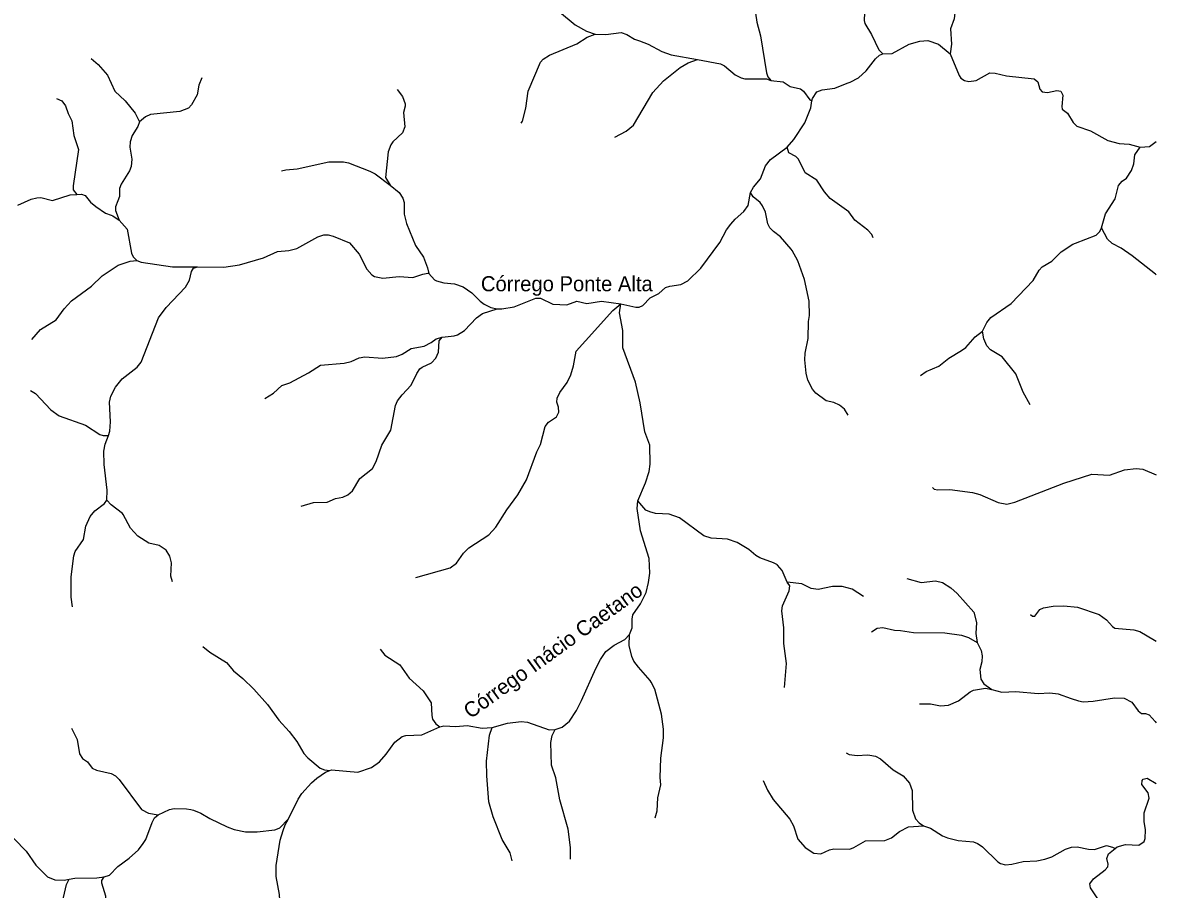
# Model space of a CAD drawing. Extents: x 473.9 to 500, y 7733.1 to 7760.8.
# Drawn here: x 492.5 to 500, y 7739.47 to 7745.21 of the extents above; entities that cross this region are included whole.
import ezdxf
from ezdxf.enums import TextEntityAlignment as Align

# ---------------------------------------------------------------- set-up
doc = ezdxf.new("R2010")
doc.units = 0
doc.header["$LTSCALE"] = 0.032
doc.layers.add('61', color=7, linetype='Continuous')
doc.layers.add('7', color=7, linetype='Continuous', lineweight=25)

msp = doc.modelspace()

# ---------------------------------------------------------------- linework, layer by layer
at = {"layer": '7'}
for points in [[(498.741, 7745.8896), (498.7715, 7745.8231), (498.7848, 7745.7768), (498.7909, 7745.7442), (498.7909, 7745.6881), (498.7725, 7745.5809), (498.741, 7745.4838), (498.6718, 7745.3155), (498.6628, 7745.2366), (498.6378, 7745.1688), (498.6434, 7745.0688), (498.6358, 7745.0043)], [(497.7661, 7745.6796), (497.8066, 7745.6735), (497.9181, 7745.6109), (497.9471, 7745.5857), (498.0085, 7745.5035), (498.0327, 7745.4566), (498.0646, 7745.3671), (498.0709, 7745.3229), (498.0654, 7745.224), (498.0697, 7745.2044), (498.115, 7745.1324), (498.1628, 7745.0297), (498.1897, 7745.0029)], [(495.744, 7745.4219), (495.9039, 7745.3332), (496.0106, 7745.3071), (496.0494, 7745.2818), (496.1528, 7745.1957), (496.2285, 7745.1548), (496.2851, 7745.1339)], [(497.3215, 7745.4526), (497.3558, 7745.2131), (497.3799, 7745.1233), (497.4205, 7744.8774), (497.4292, 7744.8521), (497.4487, 7744.828)], [(495.7972, 7744.5455), (495.8059, 7744.5583), (495.8275, 7744.6442), (495.8417, 7744.7558), (495.9231, 7744.9491), (495.9409, 7744.9675), (495.9837, 7744.9952), (496.1637, 7745.0705), (496.2327, 7745.1134), (496.2851, 7745.1339)], [(496.2851, 7745.1339), (496.3563, 7745.1326), (496.4584, 7745.1444), (496.4956, 7745.1311), (496.5463, 7745.1017), (496.5784, 7745.0899), (496.637, 7745.0685), (496.7274, 7745.0185), (496.7894, 7744.9968), (496.9629, 7744.9654)], [(498.1897, 7745.0029), (498.2513, 7745.006), (498.3641, 7745.0674), (498.4342, 7745.0874), (498.4882, 7745.0923), (498.5581, 7745.0685), (498.6358, 7745.0043)], [(492.9505, 7744.9735), (492.9975, 7744.9341), (493.0576, 7744.862), (493.1069, 7744.7558), (493.176, 7744.6923), (493.2412, 7744.6119), (493.2692, 7744.5544)], [(496.4169, 7744.4519), (496.4912, 7744.4917), (496.5402, 7744.5311), (496.6686, 7744.7468), (496.7373, 7744.826), (496.8477, 7744.9137), (496.9009, 7744.9451), (496.9629, 7744.9654)], [(496.9629, 7744.9654), (497.1146, 7744.9387), (497.1414, 7744.9241), (497.2116, 7744.8643), (497.2527, 7744.8443), (497.2768, 7744.8383), (497.4208, 7744.8375), (497.4487, 7744.828)], [(497.7209, 7744.6936), (497.7242, 7744.7076), (497.7535, 7744.7531), (497.7888, 7744.766), (497.8721, 7744.7764), (497.9545, 7744.8086), (497.9744, 7744.8164), (498.0293, 7744.8458), (498.0803, 7744.8917), (498.1412, 7744.9711), (498.1679, 7744.994), (498.1897, 7745.0029)], [(498.6358, 7745.0043), (498.6957, 7744.8602), (498.706, 7744.8431), (498.7303, 7744.8284), (498.7598, 7744.8213), (498.8066, 7744.8269), (498.8971, 7744.8784), (498.9324, 7744.8759), (499.0083, 7744.8575), (499.1919, 7744.8384), (499.2159, 7744.8186), (499.2296, 7744.7709), (499.2438, 7744.7524), (499.2791, 7744.7477), (499.3418, 7744.7604), (499.3684, 7744.7561), (499.3818, 7744.7309), (499.3739, 7744.6545), (499.3778, 7744.6372), (499.4123, 7744.6105), (499.4486, 7744.5492), (499.4739, 7744.526), (499.5641, 7744.4949), (499.678, 7744.4308), (499.7543, 7744.4093), (499.8192, 7744.4052), (499.8941, 7744.3865)], [(493.6818, 7744.8453), (493.6637, 7744.7972), (493.6511, 7744.7314), (493.6146, 7744.6667), (493.5941, 7744.6452), (493.5379, 7744.6226), (493.3437, 7744.6029), (493.3105, 7744.5863), (493.2692, 7744.5544)], [(497.4487, 7744.828), (497.5297, 7744.8191), (497.5767, 7744.7879), (497.6457, 7744.7717), (497.6644, 7744.7564), (497.7066, 7744.6991), (497.7209, 7744.6936)], [(494.9755, 7744.7672), (495.0107, 7744.722), (495.028, 7744.6737), (495.0289, 7744.6574), (495.017, 7744.6156), (495.0266, 7744.5198), (495.0113, 7744.4806), (494.9476, 7744.4216), (494.9336, 7744.402), (494.9152, 7744.3542), (494.8975, 7744.1843), (494.9301, 7744.134)], [(492.7213, 7744.7074), (492.7551, 7744.693), (492.7809, 7744.6599), (492.7971, 7744.6083), (492.8218, 7744.5602), (492.8355, 7744.464), (492.8663, 7744.3711), (492.8305, 7744.1289), (492.8313, 7744.1025), (492.8543, 7744.0724)], [(497.5573, 7744.3865), (497.6012, 7744.4357), (497.6731, 7744.546), (497.7132, 7744.6471), (497.7209, 7744.6936)], [(493.2692, 7744.5544), (493.26, 7744.523), (493.2214, 7744.464), (493.2074, 7744.4201), (493.2066, 7744.3857), (493.2185, 7744.3074), (493.2155, 7744.2567), (493.2041, 7744.2289), (493.1484, 7744.1417), (493.1376, 7744.1123), (493.1374, 7744.0586), (493.1269, 7744.0304), (493.112, 7743.9902), (493.1112, 7743.9654), (493.1349, 7743.9021)], [(497.3129, 7744.0855), (497.3336, 7744.1219), (497.3792, 7744.1762), (497.4141, 7744.2622), (497.4466, 7744.3052), (497.5573, 7744.3865)], [(498.1253, 7743.7856), (498.1171, 7743.8073), (498.0904, 7743.8358), (498.0052, 7743.9017), (497.9648, 7743.9581), (497.8404, 7744.0457), (497.8031, 7744.0904), (497.7524, 7744.1665), (497.6758, 7744.2167), (497.6757, 7744.2167), (497.6313, 7744.3061), (497.6147, 7744.3242), (497.5677, 7744.349), (497.5573, 7744.3865)], [(499.6368, 7743.8523), (499.6626, 7743.9454), (499.7273, 7744.0441), (499.7446, 7744.1135), (499.7493, 7744.1324), (499.7748, 7744.1615), (499.8016, 7744.1797), (499.8357, 7744.2324), (499.8504, 7744.2748), (499.858, 7744.3344), (499.8941, 7744.3865)], [(499.8941, 7744.3865), (499.9556, 7744.3908), (499.9993, 7744.423), (500, 7744.4235)], [(494.2108, 7744.2287), (494.2388, 7744.2361), (494.3143, 7744.2415), (494.5231, 7744.2889), (494.6213, 7744.2883), (494.6534, 7744.2818), (494.7951, 7744.2271), (494.8288, 7744.2094), (494.9301, 7744.134)], [(494.9301, 7744.134), (494.9886, 7744.0856), (495.0137, 7744.0476), (495.0217, 7744.0191), (495.0227, 7743.942), (495.037, 7743.8793), (495.0971, 7743.7349), (495.1494, 7743.6577), (495.1771, 7743.5866), (495.1851, 7743.5489)], [(492.4652, 7744.002), (492.5527, 7744.0411), (492.5912, 7744.0508), (492.6179, 7744.0515), (492.6949, 7744.0333), (492.8109, 7744.0692), (492.8543, 7744.0724)], [(492.8543, 7744.0724), (492.8862, 7744.0748), (492.9099, 7744.0649), (492.9462, 7744.0218), (492.9806, 7743.992), (493.046, 7743.948), (493.0818, 7743.9353), (493.0945, 7743.9308), (493.1349, 7743.9021)], [(496.4561, 7743.3474), (496.5542, 7743.3262), (496.578, 7743.3269), (496.6004, 7743.3381), (496.6508, 7743.3874), (496.7079, 7743.4174), (496.7513, 7743.4559), (496.78, 7743.4655), (496.8525, 7743.4756), (496.9, 7743.4999), (496.9843, 7743.584), (497.1106, 7743.7545), (497.1555, 7743.8379), (497.1828, 7743.8765), (497.2117, 7743.91), (497.2697, 7743.9608), (497.298, 7743.9996), (497.3129, 7744.0855)], [(497.96, 7742.6112), (497.9359, 7742.6504), (497.9025, 7742.6782), (497.8651, 7742.6939), (497.8153, 7742.7049), (497.7458, 7742.7573), (497.7246, 7742.7827), (497.6941, 7742.8433), (497.6814, 7742.8893), (497.6741, 7742.9775), (497.6765, 7743.0216), (497.6957, 7743.1186), (497.6973, 7743.2315), (497.7037, 7743.27), (497.7021, 7743.3661), (497.6725, 7743.5101), (497.6283, 7743.6339), (497.5892, 7743.7022), (497.5842, 7743.7109), (497.5119, 7743.792), (497.4653, 7743.8264), (497.4425, 7743.8513), (497.4297, 7743.8787), (497.4122, 7743.9552), (497.3924, 7743.9976), (497.3774, 7744.0188), (497.3307, 7744.0575), (497.3129, 7744.0855)], [(493.1349, 7743.9021), (493.1886, 7743.8427), (493.2166, 7743.684), (493.2288, 7743.6599), (493.2532, 7743.6348)], [(498.8493, 7743.1666), (498.8785, 7743.2256), (498.9045, 7743.2585), (499.0393, 7743.3515), (499.1848, 7743.5027), (499.2249, 7743.5717), (499.2439, 7743.5938), (499.3086, 7743.6314), (499.3704, 7743.6921), (499.4482, 7743.7433), (499.4659, 7743.7503), (499.6023, 7743.804), (499.6266, 7743.8278), (499.6368, 7743.8523)], [(500, 7743.5397), (499.9935, 7743.5448), (499.8394, 7743.6654), (499.767, 7743.7164), (499.7082, 7743.7472), (499.6772, 7743.7767), (499.6368, 7743.8523)], [(493.6534, 7743.5935), (493.8276, 7743.5906), (493.9319, 7743.6077), (494.0917, 7743.6534), (494.1839, 7743.6948), (494.258, 7743.7013), (494.3122, 7743.7146), (494.4505, 7743.7919), (494.4894, 7743.8046), (494.5194, 7743.8047), (494.5511, 7743.7975), (494.6603, 7743.7516), (494.723, 7743.6779), (494.7746, 7743.5773), (494.8078, 7743.5407), (494.8253, 7743.5298), (494.8809, 7743.5185), (494.9889, 7743.529), (495.0786, 7743.5219), (495.1457, 7743.5446), (495.1792, 7743.5523), (495.1851, 7743.5489)], [(492.5575, 7743.1115), (492.614, 7743.1777), (492.718, 7743.2432), (492.7714, 7743.3153), (492.819, 7743.3675), (492.952, 7743.4659), (493.0237, 7743.5329), (493.1287, 7743.6042), (493.2089, 7743.6307), (493.2532, 7743.6348)], [(493.2532, 7743.6348), (493.2816, 7743.6235), (493.4877, 7743.5939), (493.6534, 7743.5935)], [(493.0645, 7742.4768), (493.0726, 7742.5062), (493.0775, 7742.5673), (493.0711, 7742.697), (493.0796, 7742.7358), (493.1121, 7742.7958), (493.1563, 7742.8517), (493.2536, 7742.9281), (493.2806, 7742.961), (493.3962, 7743.2565), (493.4475, 7743.3234), (493.5755, 7743.4586), (493.6009, 7743.5053), (493.6141, 7743.5624), (493.6277, 7743.5848), (493.6534, 7743.5935)], [(495.1851, 7743.5489), (495.2222, 7743.5075), (495.2352, 7743.5013), (495.2852, 7743.4873), (495.3545, 7743.48), (495.4122, 7743.4607), (495.4694, 7743.4212), (495.5238, 7743.3659), (495.5521, 7743.3453), (495.5953, 7743.3249), (495.6373, 7743.3161)], [(495.6373, 7743.3161), (495.6675, 7743.3148), (495.749, 7743.329), (495.8936, 7743.3858), (495.9241, 7743.3868), (496.0056, 7743.3454), (496.0982, 7743.342), (496.1654, 7743.366), (496.2311, 7743.3495), (496.3282, 7743.3653), (496.4561, 7743.3474)], [(495.0995, 7741.5364), (495.3269, 7741.601), (495.3671, 7741.6317), (495.4142, 7741.6963), (495.449, 7741.7329), (495.5817, 7741.8189), (495.6295, 7741.8692), (495.7007, 7741.9852), (495.775, 7742.0831), (495.8314, 7742.1825), (495.9001, 7742.3682), (495.9235, 7742.4162), (495.9555, 7742.5365), (495.978, 7742.5649), (496.0302, 7742.6002), (496.0456, 7742.6317), (496.044, 7742.664), (496.0329, 7742.6974), (496.034, 7742.7232), (496.053, 7742.7619), (496.1012, 7742.8263), (496.1252, 7742.8786), (496.1434, 7742.938), (496.1596, 7743.0345), (496.2221, 7743.1035), (496.4037, 7743.304), (496.4561, 7743.3474)], [(495.2741, 7743.1282), (495.3518, 7743.1358), (495.3747, 7743.1437), (495.4216, 7743.1728), (495.501, 7743.2561), (495.5395, 7743.2839), (495.6373, 7743.3161)], [(496.5682, 7742.0447), (496.6188, 7742.1631), (496.6428, 7742.2382), (496.6501, 7742.287), (496.6485, 7742.4117), (496.6142, 7742.5015), (496.5835, 7742.6933), (496.5524, 7742.8299), (496.4687, 7743.0561), (496.4697, 7743.1728), (496.4466, 7743.2892), (496.4561, 7743.3474)], [(498.4383, 7742.874), (498.4763, 7742.9005), (498.5603, 7742.9349), (498.6276, 7742.9879), (498.711, 7743.0392), (498.7399, 7743.06), (498.8014, 7743.1305), (498.8493, 7743.1666)], [(499.1655, 7742.68), (499.1187, 7742.7635), (499.0691, 7742.885), (498.9799, 7742.9967), (498.9026, 7743.0445), (498.8791, 7743.0702), (498.8587, 7743.1176), (498.8493, 7743.1666)], [(494.1004, 7742.7211), (494.156, 7742.7576), (494.2127, 7742.8081), (494.2647, 7742.8252), (494.3889, 7742.8913), (494.467, 7742.9428), (494.6236, 7742.9557), (494.6707, 7742.9669), (494.7235, 7742.9901), (494.7604, 7742.9965), (494.8791, 7742.9885), (494.9703, 7743), (495.0084, 7743.0143), (495.0683, 7743.0526), (495.1537, 7743.0686), (495.2011, 7743.0929), (495.2327, 7743.1167), (495.2741, 7743.1282)], [(494.3401, 7742.0074), (494.4218, 7742.0336), (494.5129, 7742.0352), (494.5674, 7742.0593), (494.6158, 7742.0675), (494.649, 7742.0841), (494.6788, 7742.11), (494.7273, 7742.1913), (494.8123, 7742.257), (494.8364, 7742.3042), (494.8741, 7742.4133), (494.9341, 7742.5108), (494.9636, 7742.6744), (494.977, 7742.7057), (495.0076, 7742.7468), (495.0686, 7742.8108), (495.1045, 7742.8869), (495.1265, 7742.9169), (495.1399, 7742.9289), (495.2026, 7742.9584), (495.232, 7742.9888), (495.2485, 7743.0288), (495.2535, 7743.1028), (495.2741, 7743.1282)], [(492.5479, 7742.7734), (492.5821, 7742.755), (492.6832, 7742.6459), (492.7377, 7742.6075), (492.9125, 7742.5442), (493.0072, 7742.4834), (493.0294, 7742.4754), (493.0645, 7742.4768)], [(493.0534, 7742.0489), (493.0566, 7742.1142), (493.0358, 7742.2847), (493.0342, 7742.3722), (493.0434, 7742.4195), (493.0645, 7742.4768)], [(498.5176, 7742.131), (498.5297, 7742.1219), (498.5546, 7742.117), (498.6327, 7742.1177), (498.7826, 7742.0994), (498.8317, 7742.0855), (498.954, 7742.0334), (499.0113, 7742.0224), (499.0642, 7742.0346), (499.3884, 7742.16), (499.5731, 7742.2204), (499.6895, 7742.214), (499.7884, 7742.2492), (499.866, 7742.258), (499.9099, 7742.2525), (499.9993, 7742.2165), (500, 7742.2162)], [(492.8259, 7741.3427), (492.8169, 7741.406), (492.8176, 7741.5408), (492.8349, 7741.6803), (492.845, 7741.708), (492.8985, 7741.788), (492.9155, 7741.8762), (492.9425, 7741.9407), (492.9734, 7741.9776), (493.0387, 7742.0253), (493.0534, 7742.0489)], [(493.4885, 7741.5071), (493.4776, 7741.5452), (493.4815, 7741.6341), (493.4712, 7741.6763), (493.4462, 7741.7176), (493.4009, 7741.747), (493.3311, 7741.7624), (493.2589, 7741.8087), (493.2099, 7741.8617), (493.1613, 7741.9534), (493.1583, 7741.9591), (493.0825, 7742.0173), (493.0534, 7742.0489)], [(496.514, 7741.1576), (496.5298, 7741.2022), (496.53, 7741.261), (496.5361, 7741.2888), (496.5866, 7741.3615), (496.6237, 7741.437), (496.6398, 7741.502), (496.6469, 7741.5639), (496.6436, 7741.6623), (496.5853, 7741.8456), (496.5628, 7741.9924), (496.5682, 7742.0447)], [(497.5571, 7741.5053), (497.5227, 7741.5826), (497.4936, 7741.6182), (497.493, 7741.6189), (497.4669, 7741.6337), (497.3758, 7741.6663), (497.3482, 7741.6824), (497.3031, 7741.7215), (497.2252, 7741.7685), (497.1624, 7741.7897), (497.053, 7741.7962), (497.0051, 7741.8119), (496.8449, 7741.9321), (496.7756, 7741.9558), (496.7319, 7741.9582), (496.6851, 7741.9607), (496.6476, 7741.9708), (496.6208, 7741.9819), (496.5682, 7742.0447)], [(497.5389, 7740.8086), (497.5513, 7740.9672), (497.5338, 7741.1), (497.5337, 7741.202), (497.5218, 7741.3148), (497.5268, 7741.3479), (497.5706, 7741.4485), (497.5738, 7741.4816), (497.5571, 7741.5053)], [(498.0626, 7741.4094), (497.9862, 7741.4578), (497.9209, 7741.4762), (497.8557, 7741.4763), (497.7618, 7741.4572), (497.7159, 7741.4638), (497.6537, 7741.494), (497.5571, 7741.5053)], [(498.3476, 7741.5287), (498.4442, 7741.5029), (498.5383, 7741.5133), (498.5843, 7741.5027), (498.6396, 7741.4672), (498.6822, 7741.4304), (498.7912, 7741.3065), (498.8092, 7741.2389), (498.8062, 7741.1653), (498.8143, 7741.105)], [(499.1679, 7741.2918), (499.1809, 7741.2803), (499.1952, 7741.2794), (499.23, 7741.3252), (499.2534, 7741.3361), (499.3173, 7741.3457), (499.3879, 7741.3481), (499.4775, 7741.3392), (499.6213, 7741.2913), (499.6707, 7741.2556), (499.7095, 7741.2112), (499.7263, 7741.2014), (499.8503, 7741.1886), (499.8919, 7741.179), (499.9881, 7741.122), (500, 7741.1149)], [(498.1141, 7741.1753), (498.153, 7741.1998), (498.1888, 7741.2046), (498.2678, 7741.1862), (498.3066, 7741.1861), (498.3929, 7741.1717), (498.6007, 7741.1701), (498.7114, 7741.1539), (498.7573, 7741.138), (498.8143, 7741.105)], [(496.0215, 7740.5294), (496.0678, 7740.5441), (496.1166, 7740.5842), (496.1614, 7740.6551), (496.1946, 7740.7216), (496.2895, 7740.9338), (496.3206, 7740.9926), (496.357, 7741.0453), (496.4127, 7741.0869), (496.4821, 7741.125), (496.514, 7741.1576)], [(496.6829, 7739.9448), (496.6973, 7739.9899), (496.6999, 7740.0772), (496.7207, 7740.1639), (496.716, 7740.2108), (496.7215, 7740.3402), (496.7383, 7740.4742), (496.7383, 7740.5314), (496.724, 7740.6317), (496.681, 7740.7962), (496.6565, 7740.8422), (496.6503, 7740.8539), (496.5728, 7740.9413), (496.5422, 7740.9817), (496.5278, 7741.0131), (496.5115, 7741.0855), (496.514, 7741.1576)], [(493.6898, 7741.0785), (493.7359, 7741.0425), (493.8469, 7740.973), (493.8928, 7740.9175), (493.9544, 7740.8679), (494.0275, 7740.7957), (494.1179, 7740.6941), (494.192, 7740.5911), (494.2614, 7740.5159), (494.3107, 7740.449), (494.3582, 7740.3702), (494.3849, 7740.3413), (494.4653, 7740.2743), (494.4944, 7740.2626), (494.5297, 7740.2574)], [(494.8622, 7741.0612), (494.8928, 7741.0225), (494.9935, 7740.9577), (495.054, 7740.8692), (495.1483, 7740.7852), (495.2005, 7740.706), (495.2041, 7740.6212), (495.2102, 7740.598), (495.2315, 7740.5659), (495.2575, 7740.5464)], [(498.8143, 7741.105), (498.8413, 7741.0532), (498.8478, 7741.0173), (498.8453, 7740.9777), (498.8326, 7740.9268), (498.8392, 7740.8626), (498.8582, 7740.8328), (498.9117, 7740.7949)], [(498.4334, 7740.6992), (498.5055, 7740.6986), (498.5725, 7740.6867), (498.6244, 7740.6907), (498.69, 7740.7185), (498.7671, 7740.779), (498.7903, 7740.791), (498.869, 7740.8037), (498.9117, 7740.7949)], [(498.9117, 7740.7949), (498.9778, 7740.7772), (499.0695, 7740.7812), (499.2181, 7740.7685), (499.295, 7740.7724), (499.3512, 7740.7657), (499.4373, 7740.7352), (499.4845, 7740.7184), (499.5166, 7740.7131), (499.5819, 7740.7171), (499.7226, 7740.7387), (499.7874, 7740.737), (499.8378, 7740.71), (499.8788, 7740.6528), (499.9027, 7740.6361), (499.9285, 7740.6359), (499.9532, 7740.6266), (499.9929, 7740.5816), (500, 7740.5736)], [(492.821, 7740.5388), (492.8565, 7740.4641), (492.874, 7740.3681), (492.8931, 7740.3379), (492.9251, 7740.3153), (492.9577, 7740.273), (492.9853, 7740.2594), (493.0825, 7740.2383), (493.1102, 7740.2222), (493.135, 7740.1974), (493.284, 7739.9999), (493.3299, 7739.9752), (493.3937, 7739.9648)], [(494.5297, 7740.2574), (494.5401, 7740.2615), (494.715, 7740.2465), (494.8056, 7740.2774), (494.859, 7740.3153), (494.9034, 7740.3653), (494.9603, 7740.4463), (495.0077, 7740.4841), (495.0318, 7740.4901), (495.139, 7740.4935), (495.2575, 7740.5464)], [(495.2575, 7740.5464), (495.2843, 7740.5535), (495.3628, 7740.5487), (495.4385, 7740.5559), (495.5376, 7740.5385), (495.6052, 7740.5422)], [(495.7376, 7739.66), (495.724, 7739.7119), (495.6694, 7739.8004), (495.6099, 7739.9521), (495.5823, 7740.0499), (495.5678, 7740.2225), (495.5662, 7740.3204), (495.5863, 7740.493), (495.6052, 7740.5422)], [(495.6052, 7740.5422), (495.7064, 7740.5711), (495.7957, 7740.5831), (495.8387, 7740.5783), (495.9812, 7740.5271), (496.0215, 7740.5294)], [(496.1234, 7739.6713), (496.1227, 7739.748), (496.1081, 7739.8687), (496.0521, 7740.0641), (496.0248, 7740.2084), (495.9976, 7740.2938), (495.9918, 7740.4433), (496.0022, 7740.489), (496.0215, 7740.5294)], [(497.9479, 7740.3752), (497.9671, 7740.3641), (498.0194, 7740.3563), (498.0883, 7740.3627), (498.1045, 7740.3597), (498.1418, 7740.3529), (498.1735, 7740.3346), (498.2583, 7740.2626), (498.3249, 7740.2225), (498.3656, 7740.1742), (498.3838, 7740.1255), (498.3852, 7739.9942), (498.4067, 7739.938), (498.4293, 7739.9114), (498.4592, 7739.8913)], [(494.2556, 7739.9383), (494.3198, 7740.0683), (494.3446, 7740.1055), (494.4083, 7740.1773), (494.4439, 7740.2081), (494.5002, 7740.2458), (494.5297, 7740.2574)], [(497.3982, 7740.191), (497.4269, 7740.1275), (497.4641, 7740.0658), (497.574, 7739.9359), (497.5989, 7739.8906), (497.6268, 7739.8026), (497.6754, 7739.7476), (497.7332, 7739.7106), (497.7785, 7739.7056), (497.8362, 7739.7322), (497.8653, 7739.7388), (497.9706, 7739.7374), (497.9981, 7739.7474), (498.0745, 7739.7919), (498.2037, 7739.7942), (498.2468, 7739.8128), (498.3008, 7739.8537), (498.3598, 7739.8856), (498.4592, 7739.8913)], [(499.7265, 7739.7405), (499.7413, 7739.7521), (499.796, 7739.7677), (499.8853, 7739.7636), (499.9197, 7739.7878), (499.9271, 7739.8066), (499.9294, 7739.8643), (499.9199, 7739.9198), (499.9198, 7739.977), (499.9527, 7740.0748), (499.9454, 7740.11), (499.9043, 7740.1662), (499.9053, 7740.1911), (499.9135, 7740.2011), (499.939, 7740.207), (500, 7740.1719)], [(493.3937, 7739.9648), (493.468, 7740.0003), (493.4995, 7740.0067), (493.5806, 7740.0051), (493.6104, 7739.9992), (493.6265, 7739.996), (493.6769, 7739.9748), (493.7349, 7739.9401), (493.8497, 7739.8843), (493.8968, 7739.8668), (493.9718, 7739.851), (494.0481, 7739.8518), (494.1649, 7739.8656), (494.1827, 7739.8726), (494.1999, 7739.8793), (494.2556, 7739.9383)], [(493.037, 7739.5535), (493.072, 7739.5651), (493.1273, 7739.6219), (493.2023, 7739.6778), (493.2634, 7739.7324), (493.2934, 7739.7737), (493.3125, 7739.8001), (493.353, 7739.9146), (493.3699, 7739.9439), (493.3937, 7739.9648)], [(493.6912, 7737.9093), (493.6577, 7737.9688), (493.6116, 7738.0062), (493.6003, 7738.0154), (493.5974, 7738.0668), (493.61, 7738.1504), (493.6319, 7738.2133), (493.7196, 7738.3864), (493.9716, 7738.7369), (494.0376, 7738.8435), (494.0496, 7738.8696), (494.1733, 7739.1388), (494.2, 7739.2633), (494.2032, 7739.3203), (494.1976, 7739.4368), (494.1743, 7739.557), (494.1743, 7739.5915), (494.1743, 7739.6289), (494.2017, 7739.7973), (494.222, 7739.8595), (494.2343, 7739.8973), (494.2556, 7739.9383)], [(492.2536, 7739.8659), (492.2587, 7739.8665), (492.3135, 7739.8724), (492.3664, 7739.8554), (492.4413, 7739.8061), (492.5196, 7739.7241), (492.5834, 7739.6301), (492.6616, 7739.5527), (492.7104, 7739.5346), (492.7723, 7739.5322), (492.8039, 7739.5382)], [(498.4592, 7739.8913), (498.5057, 7739.8751), (498.5857, 7739.8247), (498.6169, 7739.8116), (498.6876, 7739.7943), (498.7909, 7739.7845), (498.8169, 7739.7748), (498.8412, 7739.7591), (498.8485, 7739.752), (498.9508, 7739.6525), (498.9682, 7739.6418), (499.0007, 7739.634), (499.044, 7739.6367), (499.1192, 7739.6557), (499.2098, 7739.6605), (499.2626, 7739.6712), (499.3092, 7739.6861), (499.3983, 7739.7379), (499.4383, 7739.7495), (499.4763, 7739.7525), (499.5519, 7739.7365), (499.5915, 7739.7349), (499.6698, 7739.762), (499.7099, 7739.7507), (499.7265, 7739.7405)], [(499.7943, 7738.9681), (499.7676, 7738.9941), (499.7518, 7739.0295), (499.7547, 7739.0446), (499.7805, 7739.0805), (499.7807, 7739.1029), (499.7507, 7739.128), (499.726, 7739.1629), (499.7138, 7739.2511), (499.6679, 7739.2941), (499.6171, 7739.4013), (499.5636, 7739.4799), (499.5607, 7739.5068), (499.5833, 7739.541), (499.661, 7739.6005), (499.6789, 7739.6206), (499.6817, 7739.6378), (499.6721, 7739.6759), (499.6826, 7739.7071), (499.7265, 7739.7405)], [(492.8039, 7739.5382), (492.843, 7739.5456), (492.9872, 7739.5473), (493.037, 7739.5535)], [(493.2053, 7739.0062), (493.1897, 7739.0345), (493.154, 7739.1369), (493.0778, 7739.2391), (493.0515, 7739.2841), (493.0422, 7739.3172), (493.0462, 7739.4255), (493.0198, 7739.5121), (493.02, 7739.529), (493.037, 7739.5535)], [(492.6452, 7738.6987), (492.6541, 7738.7489), (492.6469, 7739.0153), (492.651, 7739.1606), (492.6735, 7739.2246), (492.7318, 7739.3132), (492.7545, 7739.3588), (492.7874, 7739.5024), (492.8039, 7739.5382)]]:
    msp.add_lwpolyline(points, dxfattribs=at)

# ---------------------------------------------------------------- texts
at = {"layer": '61'}
msp.add_text('Córrego Ponte Alta', height=0.1, dxfattribs=at).set_placement((496.0983, 7743.4314), align=Align.CENTER)
msp.add_text('Córrego Inácio Caetano', height=0.1, rotation=35.91, dxfattribs=at).set_placement((496.0358, 7741.0131), align=Align.CENTER)

doc.saveas('drawing.dxf')
